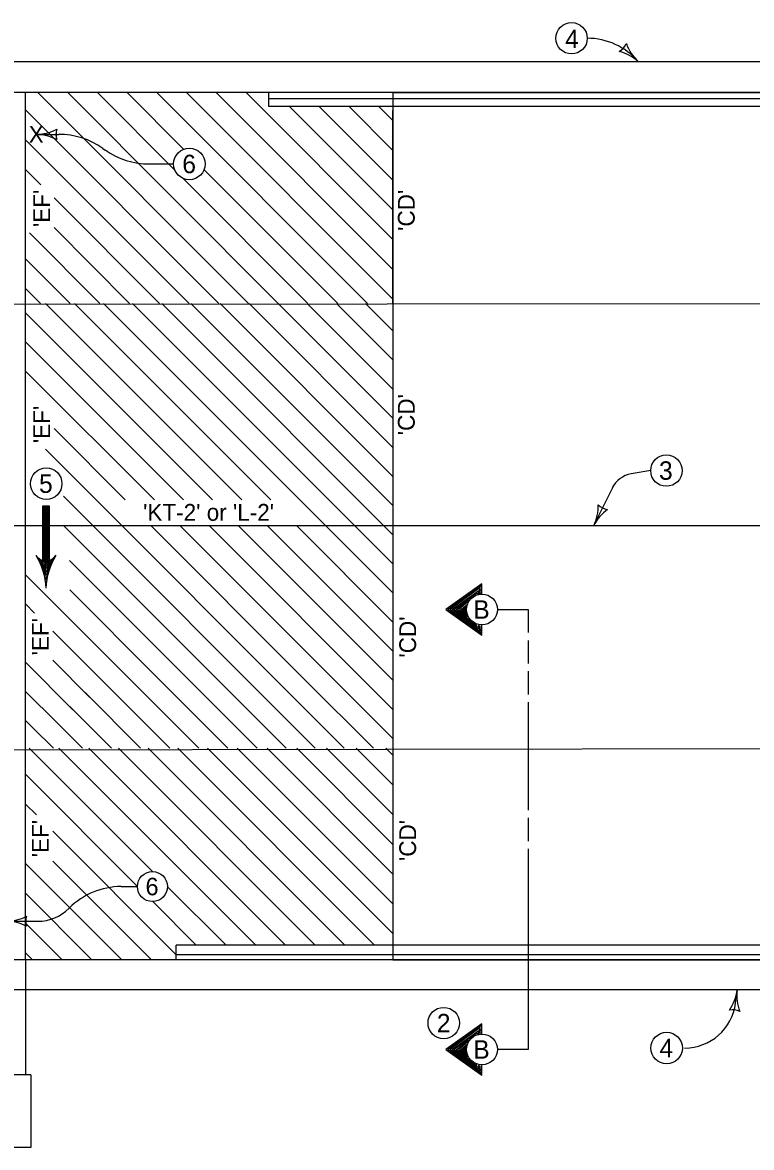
# Model space of a CAD drawing. Extents: x 5546 to 81668, y 3174 to 15999.
# Drawn here: x 25088 to 25817, y 5673 to 6796 of the extents above; entities that cross this region are included whole.
import ezdxf

# ---------------------------------------------------------------- set-up
doc = ezdxf.new("R2010")
doc.units = 0
doc.layers.add('PS_BOLT', color=7, linetype='Continuous')
doc.layers.add('PS_DIM', color=7, linetype='Continuous')

msp = doc.modelspace()

# ---------------------------------------------------------------- linework, layer by layer
msp.add_line((25828.3, 6726.2), (24281.5, 6726.2))
at = {"layer": 'PS_BOLT'}
for p, q in [((25715.8, 6348.8), (25696.2, 6345.5)), ((25677.5, 6331.5), (25658.8, 6293.7)), ((25098.5, 6092.1), (25091.2, 6099.3)), ((26267.5, 6071.6), (24281.5, 6068.3)), ((25593.4, 5971.1), (25593.4, 5770.9)), ((25186.8, 5933.5), (25203, 5933.5)), ((25072.2, 5898.9), (25103.5, 5898.9)), ((25800.5, 5817.2), (25802.2, 5830.3))]:
    msp.add_line(p, q, dxfattribs=at)
for points in [[(25562.6, 6210.1), (25593.4, 6210.1), (25593.4, 6187)], [(25593.4, 6179.3), (25593.4, 6156.2)], [(25593.4, 6148.5), (25593.4, 6125.3)], [(25593.4, 6117.6), (25593.4, 6009.7)], [(25593.4, 6002), (25593.4, 5978.8)], [(25593.4, 5782.3), (25593.4, 5770.9), (25562.6, 5770.9)]]:
    msp.add_lwpolyline(points, dxfattribs=at)
for centre, radius, start, end in [((25652.5, 6713.6), 66.8, 40.5607, 90), ((25700.5, 6320.1), 25.7, 99.5323, 153.7542), ((25186.8, 5860.1), 73.4, 90, 135), ((25103.5, 5943), 44.1, 270, 315), ((25749.6, 5823.7), 51.4, 270, 352.7713)]:
    msp.add_arc(centre, radius, start, end, dxfattribs=at)
at = {"layer": 'PS_DIM'}
for p, q in [((26204.1, 6757), (24281.5, 6757)), ((25091.2, 6515.7), (25091.2, 6726.2)), ((25314, 6515.7), (25103.6, 6726.2)), ((25343.7, 6515.7), (25133.3, 6726.2)), ((25240.7, 6648.4), (25163, 6726.2)), ((25249.4, 6669.4), (25192.7, 6726.2)), ((25432.8, 6515.7), (25222.4, 6726.2)), ((25458.2, 6520), (25252.1, 6726.2)), ((25458.2, 6549.7), (25281.8, 6726.2)), ((25458.2, 6579.4), (25311.5, 6726.2)), ((25334.2, 6712.3), (25334.2, 6726.2)), ((26118.6, 6720), (25334.2, 6720)), ((25828.3, 6726.2), (25458.2, 6726.2)), ((25458.2, 6726.2), (25828.3, 6726.2)), ((25458.2, 6726.2), (25458.2, 6071.6)), ((26118.6, 6726.2), (25552, 6726.2)), ((25284.3, 6515.7), (25091.2, 6708.8)), ((26231.7, 6712.3), (25334.2, 6712.3)), ((25458.2, 6609.1), (25355, 6712.3)), ((25458.2, 6638.8), (25384.7, 6712.3)), ((25458.2, 6668.5), (25414.4, 6712.3)), ((25458.2, 6698.2), (25444.1, 6712.3)), ((25458.2, 6515.7), (25458.3, 6708.4)), ((25091.2, 6515.7), (25091.2, 6700.7)), ((25101.5, 6684.4), (25124.3, 6684.4)), ((25254.6, 6515.7), (25091.2, 6679.1)), ((25168.5, 6670.4), (25170.8, 6668.8)), ((25106.4, 6634.2), (25091.2, 6649.4)), ((25215, 6654.9), (25239.2, 6654.9)), ((25403.1, 6515.7), (25269.4, 6649.4)), ((25373.4, 6515.7), (25248.1, 6641)), ((25224.9, 6515.7), (25119.7, 6621)), ((25165.5, 6515.7), (25095.2, 6586)), ((25195.2, 6515.7), (25119.7, 6591.3)), ((25135.8, 6515.7), (25091.2, 6560.3)), ((25106.1, 6515.7), (25091.2, 6530.6)), ((24281.5, 6514.6), (26314.2, 6515.7)), ((25091.2, 6071.6), (25091.2, 6515.7)), ((25119.5, 6507.2), (25111, 6515.7)), ((25161.9, 6493.9), (25140.1, 6515.7)), ((25210.2, 6474.6), (25169.2, 6515.7)), ((25236.2, 6477.7), (25198.2, 6515.7)), ((25253.6, 6489.4), (25227.3, 6515.7)), ((25458.2, 6313.9), (25256.4, 6515.7)), ((25458.2, 6342.9), (25285.5, 6515.7)), ((25458.2, 6372), (25314.5, 6515.7)), ((25458.2, 6401.1), (25343.6, 6515.7)), ((25458.2, 6430.2), (25372.7, 6515.7)), ((25458.2, 6459.2), (25401.8, 6515.7)), ((25458.2, 6488.3), (25430.8, 6515.7)), ((25278.1, 6319.5), (25091.2, 6506.4)), ((25307.2, 6319.5), (25119.5, 6507.2)), ((25336.3, 6319.5), (25161.9, 6493.9)), ((25458.2, 6284.8), (25253.6, 6489.4)), ((25249.1, 6319.5), (25091.2, 6477.3)), ((25210.2, 6474.6), (25217.1, 6467.8)), ((25344.7, 6340.2), (25210.2, 6474.6)), ((25458.2, 6255.7), (25236.2, 6477.7)), ((25220, 6319.5), (25091.2, 6448.2)), ((25458.7, 6405.8), (25458.2, 6406.2)), ((25190.9, 6319.5), (25119.7, 6390.7)), ((25409.7, 6071.6), (25111, 6370.3)), ((25458.2, 6226.6), (25344.7, 6340.2)), ((25380.6, 6071.6), (25129, 6323.3)), ((25111.6, 6259), (25111.6, 6313.5)), ((25828.3, 6293.7), (23947.1, 6293.7)), ((25351.6, 6071.6), (25129.5, 6293.7)), ((25369.4, 6141), (25216.8, 6293.7)), ((25383.9, 6155.6), (25245.8, 6293.7)), ((25458.2, 6110.3), (25274.9, 6293.7)), ((25458.2, 6139.4), (25304, 6293.7)), ((25458.2, 6168.5), (25333.1, 6293.7)), ((25458.2, 6197.6), (25362.1, 6293.7)), ((25108.3, 6259.1), (25108.3, 6259.1)), ((25114.7, 6259.1), (25114.7, 6259.1)), ((25322.5, 6071.6), (25135, 6259.1)), ((25206.1, 6129.9), (25091.2, 6244.7)), ((25222.5, 6142.5), (25135.4, 6229.6)), ((25100.3, 6206.6), (25091.2, 6215.7)), ((25177.6, 6129.3), (25118.4, 6188.5)), ((25138.6, 6110.1), (25091.2, 6157.5)), ((25155.1, 6122.7), (25118.4, 6159.4)), ((25458.2, 6081.3), (25383.9, 6155.6)), ((25293.4, 6071.6), (25218.4, 6146.6)), ((25438.8, 6071.6), (25369.4, 6141)), ((25123.1, 6096.5), (25091.2, 6128.4)), ((25206.2, 6071.6), (25150.7, 6127.1)), ((25235.3, 6071.6), (25177.6, 6129.3)), ((25264.4, 6071.6), (25206.1, 6129.9)), ((25177.1, 6071.6), (25135.5, 6113.2)), ((25119, 6071.6), (25098.5, 6092.1)), ((25148.1, 6071.6), (25123.1, 6096.5)), ((25091.2, 5861.1), (25091.2, 6071.6)), ((25218, 5948.5), (25094.9, 6071.6)), ((25321.2, 5875), (25124.6, 6071.6)), ((25350.9, 5875), (25154.3, 6071.6)), ((25380.6, 5875), (25184, 6071.6)), ((25410.3, 5875), (25213.7, 6071.6)), ((25440, 5875), (25243.4, 6071.6)), ((25458.2, 5886.6), (25273.1, 6071.6)), ((25458.2, 5916.2), (25302.8, 6071.6)), ((25458.2, 5945.9), (25332.5, 6071.6)), ((25458.2, 5975.6), (25362.2, 6071.6)), ((25458.2, 6005.3), (25391.9, 6071.6)), ((25458.2, 6035), (25421.6, 6071.6)), ((25458.2, 6064.7), (25451.3, 6071.6)), ((25458.2, 6071.6), (25458.2, 5886.6)), ((25458.2, 6071.6), (25458.2, 5861.1)), ((25203.2, 5933.7), (25091.2, 6045.6)), ((25102.1, 6005.1), (25091.2, 6015.9)), ((25241.7, 5865.5), (25118.4, 5988.7)), ((25186.6, 5861.1), (25091.2, 5956.5)), ((25216.3, 5861.1), (25118.4, 5959)), ((25291.5, 5875), (25232.8, 5933.7)), ((25156.9, 5861.1), (25091.2, 5926.8)), ((25261.8, 5875), (25218, 5918.9)), ((25127.2, 5861.1), (25091.2, 5897.1)), ((25241.7, 5860.4), (25241.7, 5875)), ((26147.6, 5875), (25241.7, 5875)), ((25097.5, 5861.1), (25091.2, 5867.4)), ((26128.7, 5865.5), (25241.7, 5865.5)), ((26118.6, 5860.4), (24281.5, 5860.4)), ((25091.2, 5861.1), (25091.2, 5745.4)), ((25791.3, 5830.3), (24281.5, 5830.3)), ((26118.6, 5830.3), (25791.3, 5830.3)), ((25096.4, 5745.4), (25079.9, 5745.4)), ((25096.4, 5745.4), (25096.4, 5673)), ((25096.4, 5673), (25079.9, 5673))]:
    msp.add_line(p, q, dxfattribs=at)
msp.add_lwpolyline([(25458.2, 5860.4), (26118.6, 5860.4), (26147.6, 5875), (26174.1, 5875), (26248.1, 5886.6), (26250.9, 5885.4), (26253.7, 5886.6), (26339.2, 6700.7), (26336.4, 6701.9), (26333.6, 6700.7), (26259.6, 6712.3), (26231.7, 6712.3), (26204.1, 6726.2), (25458.2, 6726.2)], close=True, dxfattribs=at)
for points in [[(25091.2, 6515.7), (25091.2, 6515.7)], [(25108.5, 6259.1), (25108.5, 6313.5), (25114.7, 6313.5), (25114.7, 6259.1), (25109.4, 6259.2), (25109.2, 6312.8), (25114.1, 6312.7), (25113.9, 6260.3), (25110.3, 6260.1), (25110, 6312), (25113.3, 6311.9), (25113.3, 6261), (25111, 6260.8), (25110.7, 6311.4), (25112.6, 6311.4), (25112.5, 6261.6)], [(25104.5, 6260.5), (25108.2, 6258.2), (25113.6, 6258), (25118.3, 6259.9), (25115, 6251.9), (25112.2, 6242.5), (25111.6, 6239.8), (25110.3, 6246.6), (25106.8, 6256.5), (25105.3, 6259.5), (25116.7, 6258.4), (25111.8, 6243.9), (25107.5, 6258), (25115.4, 6257.5), (25111.8, 6247.5), (25109.5, 6256.7), (25114.1, 6257.1), (25112, 6250.7), (25110.7, 6255.6), (25112.8, 6255.8), (25112.2, 6253.5)], [(25547.2, 6225.5), (25547.2, 6235.8), (25511.2, 6210.1), (25547.2, 6184.4), (25547.2, 6194.7)], [(25546.2, 6193.7), (25546.2, 6186.3), (25513.1, 6210.1), (25546.3, 6234.2), (25546.1, 6226.3), (25544.7, 6225.9), (25545.2, 6231.6), (25515.3, 6210.1), (25545.2, 6188.3), (25544.9, 6193.9), (25543.8, 6194.1), (25543.9, 6190.4), (25517.3, 6210.2), (25544, 6229), (25543.4, 6225.8), (25542.3, 6225.5), (25542.4, 6226.6), (25519.6, 6209.9), (25542.8, 6192.4), (25541.7, 6194.3), (25521.6, 6209.8), (25533.9, 6219.5), (25533.1, 6217.7), (25523.7, 6209.7), (25532.8, 6202.7), (25532, 6204.6), (25525.6, 6209.4), (25532, 6214.9), (25531.3, 6212.5), (25527.2, 6209.4), (25531.4, 6206.1), (25531.2, 6207.8), (25528.8, 6209.3), (25531.1, 6210.7), (25531, 6209.2), (25530.2, 6209.3)], [(25091.2, 6071.6), (25091.2, 6071.6)], [(25547.2, 5786.3), (25547.2, 5796.6), (25511.2, 5770.9), (25547.2, 5745.2), (25547.2, 5755.5)], [(25546.2, 5754.5), (25546.2, 5747), (25513.1, 5770.9), (25546.3, 5795), (25546.1, 5787.1), (25544.7, 5786.7), (25545.2, 5792.4), (25515.3, 5770.9), (25545.2, 5749.1), (25544.9, 5754.6), (25543.8, 5754.9), (25543.9, 5751.2), (25517.3, 5771), (25544, 5789.8), (25543.4, 5786.6), (25542.3, 5786.3), (25542.4, 5787.4), (25519.6, 5770.7), (25542.8, 5753.2), (25541.7, 5755.1), (25521.6, 5770.5), (25533.9, 5780.3), (25533.1, 5778.5), (25523.7, 5770.5), (25532.8, 5763.5), (25532, 5765.3), (25525.6, 5770.2), (25532, 5775.7), (25531.3, 5773.3), (25527.2, 5770.2), (25531.4, 5766.9), (25531.2, 5768.6), (25528.8, 5770.1), (25531.1, 5771.5), (25531, 5770), (25530.2, 5770.1)]]:
    msp.add_lwpolyline(points, dxfattribs=at)
for centre, radius in [((25636.7, 6780.4), 15.7), ((25254.9, 6654.9), 15.7), ((25731.5, 6348.8), 15.7), ((25111.9, 6335.7), 15.7), ((25547.2, 6210.1), 15.4), ((25218, 5933.5), 15), ((25509, 5797.2), 15.7), ((25547.2, 5770.9), 15.4), ((25731.7, 5772.3), 15.7)]:
    msp.add_circle(centre, radius, dxfattribs=at)
for centre, radius, start, end in [((25675.9, 6782.2), 17.1, 299.4947, 334.9614), ((25733.4, 6789.6), 44.4, 199.1556, 227.2281), ((25673.1, 6724.4), 44.4, 47.2281, 75.3006), ((25101.5, 6728.8), 44.4, 270, 298.0725), ((25101.5, 6728.8), 44.4, 270, 298.0725), ((25101.5, 6640), 44.4, 61.9275, 90), ((25101.5, 6640), 44.4, 61.9275, 90), ((25138.8, 6684.4), 17.1, 162.2666, 197.7334), ((25138.7, 6684.4), 17.1, 162.2666, 197.7334), ((25124.3, 6607.3), 77.1, 55.0007, 90), ((25215, 6732), 77.1, 235.0001, 270), ((25619, 6313.3), 44.4, 333.7545, 1.8269), ((25675.2, 6327), 17.1, 226.0211, 261.4878), ((25698.6, 6274), 44.4, 125.682, 153.7545), ((25111.6, 6270.3), 11.6, 211.7147, 328.2853), ((25045.4, 6229.3), 66.3, 1.6842, 31.7143), ((25177.9, 6229.3), 66.3, 148.2857, 178.3158), ((25072.2, 5941.2), 42.3, 270, 298.0725), ((25072.2, 5856.6), 42.3, 61.9275, 90), ((25107.7, 5898.9), 16.3, 162.2666, 197.7334), ((25758.2, 5835.9), 44.4, 324.6988, 352.7713), ((25846.2, 5824.7), 44.4, 172.7713, 200.8438), ((25797.5, 5793.4), 17.1, 65.0379, 100.5046)]:
    msp.add_arc(centre, radius, start, end, dxfattribs=at)

# ---------------------------------------------------------------- texts
at = {"layer": 'PS_BOLT'}
for s, height, p in [('4', 18.4, (25630.3, 6770.5)), ('X', 16.8, (25094.4, 6676)), ('6', 18.4, (25247.8, 6645.7)), ('3', 18.4, (25724.1, 6339.6)), ('5', 18.4, (25104.7, 6326.5)), ("'KT-2' or 'L-2'", 16.8, (25208.7, 6298.7)), ('B', 18.4, (25538.5, 6200.9)), ('6', 17.5, (25211.1, 5924.8)), ('2', 18.4, (25502.1, 5788)), ('B', 18.4, (25538.5, 5761.7)), ('4', 18.4, (25724.6, 5763.1))]:
    msp.add_text(s, height=height, dxfattribs=at).set_placement(p)
for s, p in [("'EF'", (25115.7, 6591.9)), ("'CD'", (25480, 6588.1)), ("'CD'", (25480, 6384.1)), ("'EF'", (25115.7, 6376.2)), ("'EF'", (25114.4, 6164.3)), ("'CD'", (25481.4, 6162.1)), ("'EF'", (25114.4, 5962.8)), ("'CD'", (25481.4, 5959))]:
    msp.add_text(s, height=16.8, rotation=90, dxfattribs=at).set_placement(p)

doc.saveas('drawing.dxf')
